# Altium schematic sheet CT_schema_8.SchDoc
size 205 x 258 mm
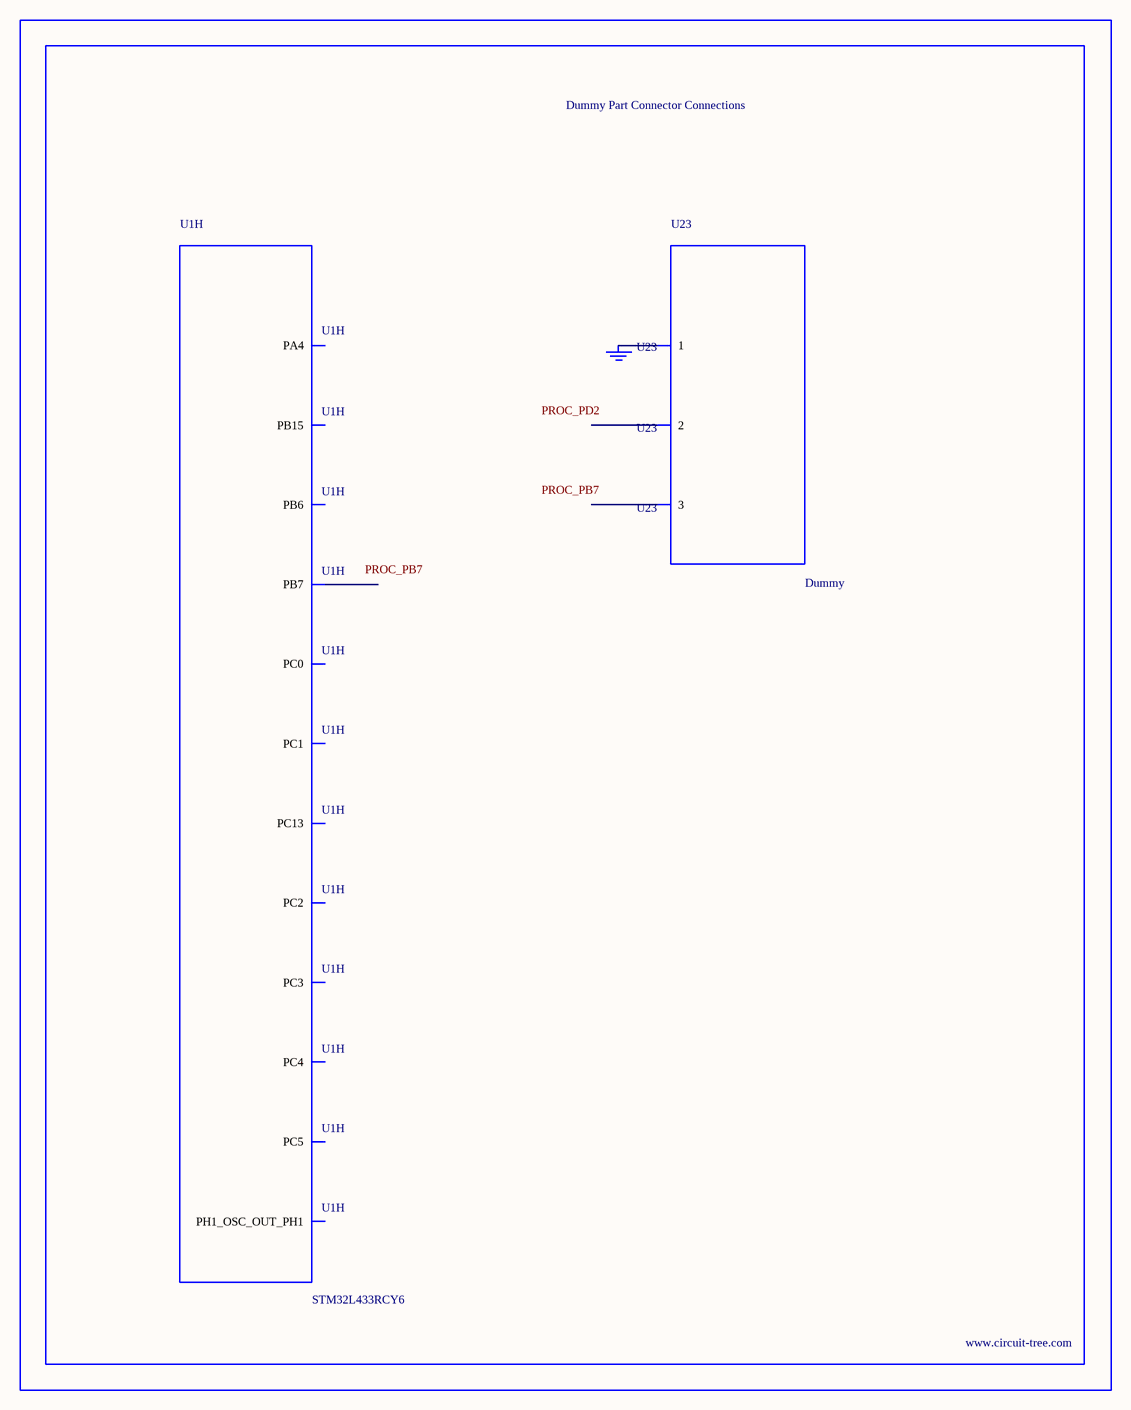
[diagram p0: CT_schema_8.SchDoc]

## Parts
BORDER7  (no value)
GND_INSTANCE_7_0  (no value)
U1  STM32L433RCY6  [WLCSP64]  (part H of 8)
U23  Dummy  [DUMMY_PACKAGE_231]

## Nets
NetGND_INSTANCE_7_0_0: GND_INSTANCE_7_0.0(GND) U23.1

Not connected (* = marked no-connect by the designer): U1 A6(PB7) B5(PB6) B8(PC13) D4(PC4) D5(PC0) D7(PH1_OSC_OUT_PH1) E4(PC5) E5(PA4) E6(PC3) E7(PC2) E8(PC1) F2(PB15); U23 2 3

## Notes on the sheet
- Labels drawn without touching a wire or pin: PROC_PB7, PROC_PD2

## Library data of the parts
BORDER7 = BORDER_PAGE7
GND_INSTANCE_7_0 = GND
